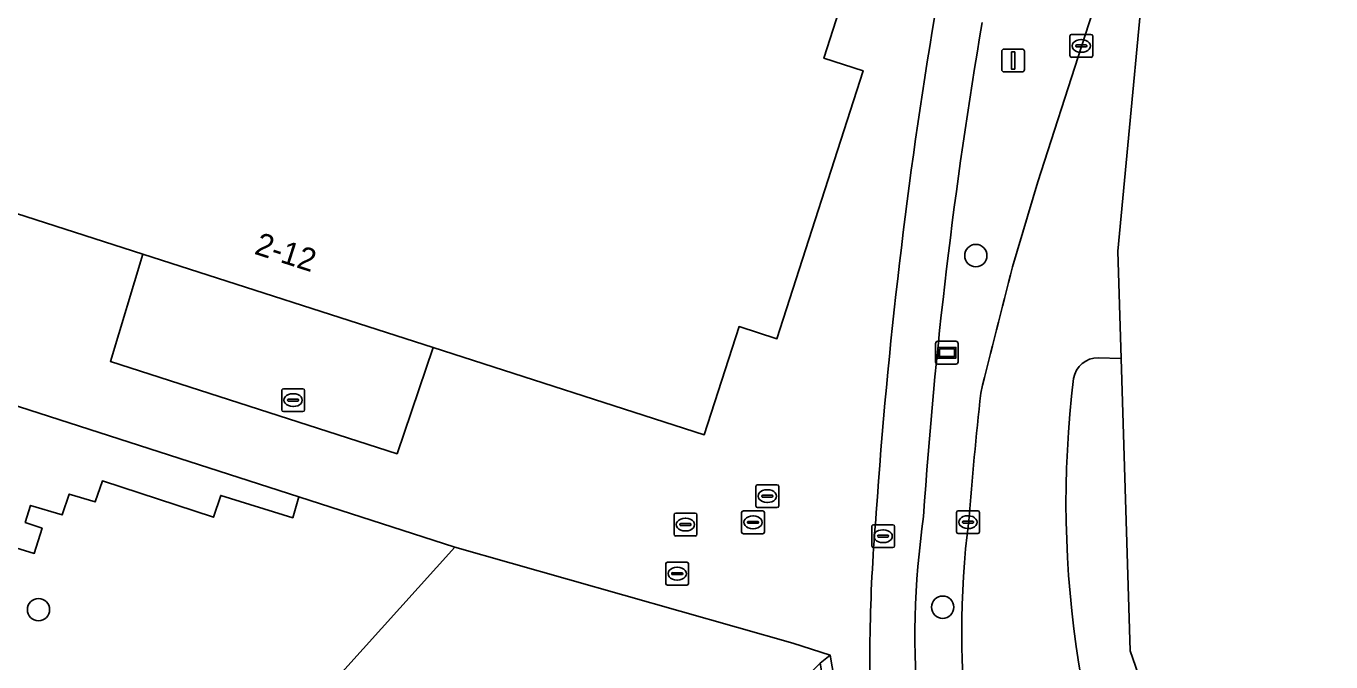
# Model space of a CAD drawing. Extents: x 160675 to 161153, y 383241 to 383714.
# Drawn here: x 161039 to 161096.1, y 383296.7 to 383324.6 of the extents above; entities that cross this region are included whole.
import ezdxf

# ---------------------------------------------------------------- set-up
doc = ezdxf.new("R2010")
doc.units = 0
for name, color, linetype in [('IMGEO_Berm_groen', 7, 'Continuous'), ('IMGEO_Boom', 7, 'Continuous'), ('IMGEO_Brandkraan', 7, 'Continuous'), ('IMGEO_Fietspad_gesloten', 7, 'Continuous'), ('IMGEO_Groenvoorziening', 7, 'Continuous'), ('IMGEO_Kolk', 7, 'Continuous'), ('IMGEO_Lichtmast', 7, 'Continuous'), ('IMGEO_Pand', 7, 'Continuous'), ('IMGEO_Pand_nummerreeks', 7, 'Continuous'), ('IMGEO_Reclamebord', 7, 'Continuous'), ('IMGEO_Rijbaan_lokaal_gesloten', 7, 'Continuous'), ('IMGEO_Rioolput', 7, 'Continuous'), ('IMGEO_Verkeerseiland_groen', 7, 'Continuous'), ('IMGEO_Voetpad_open', 7, 'Continuous')]:
    doc.layers.add(name, color=color, linetype=linetype)

msp = doc.modelspace()

# ---------------------------------------------------------------- linework, layer by layer
at = {"layer": 'IMGEO_Berm_groen'}
msp.add_lwpolyline([(161082.189, 383314.05), (161083.295, 383317.77), (161085.211, 383323.707), (161089.61, 383337.285), (161096.146, 383357.606)], dxfattribs=at)
for centre, radius, start, end in [((161292.407, 383288.685), 214.601, 170.32297, 176.14495), ((161519.479, 383201.174), 451.624, 165.52635, 166.25015), ((161266.822, 383288.222), 187.128, 173.77371, 175.49626), ((161115.333, 383297.8), 37.42, 171.8377, 198.7986), ((161117.973, 383298.123), 38.005, 172.7545, 202.1608)]:
    msp.add_arc(centre, radius, start, end, dxfattribs=at)
at = {"layer": 'IMGEO_Boom'}
for centre in [(161080.583, 383314.544), (161039.499, 383299.033), (161079.131, 383299.138)]:
    msp.add_circle(centre, 0.489, dxfattribs=at)
at = {"layer": 'IMGEO_Brandkraan'}
for p, q in [((161066.993, 383300.183), (161066.993, 383301.035)), ((161067.068, 383301.109), (161067.92, 383301.109)), ((161067.481, 383300.889), (161067.506, 383300.889)), ((161067.994, 383301.035), (161067.994, 383300.183)), ((161067.92, 383300.109), (161067.068, 383300.109)), ((161067.252, 383300.603), (161067.252, 383300.615)), ((161067.69, 383300.566), (161067.292, 383300.566)), ((161067.295, 383300.652), (161067.693, 383300.652)), ((161067.504, 383300.329), (161067.479, 383300.329)), ((161067.736, 383300.615), (161067.736, 383300.603))]:
    msp.add_line(p, q, dxfattribs=at)
for points in [[(161066.993, 383300.183), (161066.993, 383301.035)], [(161067.068, 383301.109), (161067.92, 383301.109)], [(161067.994, 383301.035), (161067.994, 383300.183)], [(161067.92, 383300.109), (161067.068, 383300.109)]]:
    msp.add_lwpolyline(points, dxfattribs=at)
for centre, radius, start, end in [((161067.07, 383301.033), 0.0765, 91.552, 178.448), ((161067.07, 383301.033), 0.0765, 91.552, 178.448), ((161067.918, 383301.033), 0.0765, 1.552, 88.448), ((161067.918, 383301.033), 0.0765, 1.552, 88.448), ((161067.07, 383300.185), 0.0765, 181.552, 268.448), ((161067.07, 383300.185), 0.0765, 181.552, 268.448), ((161067.292, 383300.612), 0.0403, 85.8775, 175.7526), ((161067.289, 383300.602), 0.0366, 178.938, 274.7102), ((161067.693, 383300.609), 0.043, 264.8664, 352.4533), ((161067.697, 383300.614), 0.0386, 1.7309, 96.639), ((161067.918, 383300.185), 0.0765, 271.552, 358.448), ((161067.918, 383300.185), 0.0765, 271.552, 358.448)]:
    msp.add_arc(centre, radius, start, end, dxfattribs=at)
for centre, major_axis, ratio, start_param, end_param in [((161067.48, 383300.609), (-0.387, 0.002), 0.722429, 4.712389, 7.853982), ((161067.505, 383300.609), (-0.39, 0.002), 0.717154, 1.570796, 4.712389)]:
    msp.add_ellipse(centre, major_axis=major_axis, ratio=ratio, start_param=start_param, end_param=end_param, dxfattribs=at)
at = {"layer": 'IMGEO_Fietspad_gesloten'}
for centre, radius, start, end in [((161299.542, 383288.005), 223.844, 170.47225, 176.08333), ((161292.407, 383288.685), 214.601, 170.32297, 176.14495), ((161155.631, 383296.511), 79.7, 175.11724, 182.3005), ((161115.333, 383297.8), 37.42, 171.8377, 198.7986)]:
    msp.add_arc(centre, radius, start, end, dxfattribs=at)
at = {"layer": 'IMGEO_Groenvoorziening'}
msp.add_lwpolyline([(161037.053, 383284.483), (161040.997, 383283.21), (161057.751, 383301.776), (161050.91, 383303.976), (161050.64, 383303.056), (161047.486, 383304.035), (161047.165, 383303.078), (161042.298, 383304.675), (161041.978, 383303.75), (161040.846, 383304.095), (161040.543, 383303.185), (161039.154, 383303.596), (161038.919, 383302.854), (161039.655, 383302.597), (161039.31, 383301.493), (161037.358, 383302.095)], dxfattribs=at)
at = {"layer": 'IMGEO_Kolk'}
for p, q in [((161084.703, 383323.305), (161084.703, 383324.157)), ((161084.778, 383324.231), (161085.63, 383324.231)), ((161085.704, 383324.157), (161085.704, 383323.305)), ((161084.962, 383323.725), (161084.962, 383323.737)), ((161085.4, 383323.688), (161085.002, 383323.688)), ((161085.005, 383323.774), (161085.403, 383323.774)), ((161085.191, 383324.011), (161085.216, 383324.011)), ((161085.446, 383323.737), (161085.446, 383323.725)), ((161085.63, 383323.231), (161084.778, 383323.231)), ((161085.214, 383323.451), (161085.189, 383323.451)), ((161050.233, 383308.712), (161051.085, 383308.712)), ((161050.158, 383307.786), (161050.158, 383308.638)), ((161050.417, 383308.206), (161050.417, 383308.218)), ((161050.855, 383308.169), (161050.457, 383308.169)), ((161050.46, 383308.255), (161050.858, 383308.255)), ((161050.646, 383308.492), (161050.671, 383308.492)), ((161050.901, 383308.218), (161050.901, 383308.206)), ((161051.159, 383308.638), (161051.159, 383307.786)), ((161051.085, 383307.712), (161050.233, 383307.712)), ((161050.669, 383307.932), (161050.644, 383307.932)), ((161067.355, 383302.333), (161067.355, 383303.185)), ((161067.43, 383303.259), (161068.282, 383303.259)), ((161067.843, 383303.039), (161067.868, 383303.039)), ((161068.356, 383303.185), (161068.356, 383302.333)), ((161079.737, 383302.439), (161079.737, 383303.291)), ((161079.812, 383303.365), (161080.664, 383303.365)), ((161080.225, 383303.145), (161080.25, 383303.145)), ((161080.738, 383303.291), (161080.738, 383302.439)), ((161067.614, 383302.753), (161067.614, 383302.765)), ((161068.052, 383302.716), (161067.654, 383302.716)), ((161067.657, 383302.802), (161068.055, 383302.802)), ((161067.866, 383302.479), (161067.841, 383302.479)), ((161068.098, 383302.765), (161068.098, 383302.753)), ((161079.996, 383302.859), (161079.996, 383302.871)), ((161080.434, 383302.822), (161080.036, 383302.822)), ((161080.039, 383302.908), (161080.437, 383302.908)), ((161080.248, 383302.585), (161080.223, 383302.585)), ((161080.48, 383302.871), (161080.48, 383302.859)), ((161068.282, 383302.259), (161067.43, 383302.259)), ((161080.664, 383302.365), (161079.812, 383302.365))]:
    msp.add_line(p, q, dxfattribs=at)
for points in [[(161084.703, 383323.305), (161084.703, 383324.157)], [(161084.778, 383324.231), (161085.63, 383324.231)], [(161085.704, 383324.157), (161085.704, 383323.305)], [(161085.63, 383323.231), (161084.778, 383323.231)], [(161050.233, 383308.712), (161051.085, 383308.712)], [(161050.158, 383307.786), (161050.158, 383308.638)], [(161051.159, 383308.638), (161051.159, 383307.786)], [(161051.085, 383307.712), (161050.233, 383307.712)], [(161067.355, 383302.333), (161067.355, 383303.185)], [(161067.43, 383303.259), (161068.282, 383303.259)], [(161068.356, 383303.185), (161068.356, 383302.333)], [(161079.737, 383302.439), (161079.737, 383303.291)], [(161079.812, 383303.365), (161080.664, 383303.365)], [(161080.738, 383303.291), (161080.738, 383302.439)], [(161068.282, 383302.259), (161067.43, 383302.259)], [(161080.664, 383302.365), (161079.812, 383302.365)]]:
    msp.add_lwpolyline(points, dxfattribs=at)
for centre, radius, start, end in [((161084.78, 383324.155), 0.0765, 91.552, 178.448), ((161084.78, 383324.155), 0.0765, 91.552, 178.448), ((161085.628, 383324.155), 0.0765, 1.552, 88.448), ((161085.628, 383324.155), 0.0765, 1.552, 88.448), ((161085.002, 383323.734), 0.0403, 85.8775, 175.7526), ((161084.999, 383323.724), 0.0366, 178.938, 274.7102), ((161085.403, 383323.731), 0.043, 264.8664, 352.4533), ((161085.407, 383323.736), 0.0386, 1.7309, 96.639), ((161084.78, 383323.307), 0.0765, 181.552, 268.448), ((161084.78, 383323.307), 0.0765, 181.552, 268.448), ((161085.628, 383323.307), 0.0765, 271.552, 358.448), ((161085.628, 383323.307), 0.0765, 271.552, 358.448), ((161050.235, 383308.636), 0.0765, 91.552, 178.448), ((161050.235, 383308.636), 0.0765, 91.552, 178.448), ((161051.083, 383308.636), 0.0765, 1.552, 88.448), ((161051.083, 383308.636), 0.0765, 1.552, 88.448), ((161050.457, 383308.215), 0.0403, 85.8775, 175.7526), ((161050.454, 383308.205), 0.0366, 178.938, 274.7102), ((161050.858, 383308.212), 0.043, 264.8664, 352.4533), ((161050.862, 383308.217), 0.0386, 1.7309, 96.639), ((161050.235, 383307.788), 0.0765, 181.552, 268.448), ((161050.235, 383307.788), 0.0765, 181.552, 268.448), ((161051.083, 383307.788), 0.0765, 271.552, 358.448), ((161051.083, 383307.788), 0.0765, 271.552, 358.448), ((161067.432, 383303.183), 0.0765, 91.552, 178.448), ((161067.432, 383303.183), 0.0765, 91.552, 178.448), ((161068.28, 383303.183), 0.0765, 1.552, 88.448), ((161068.28, 383303.183), 0.0765, 1.552, 88.448), ((161079.814, 383303.289), 0.0765, 91.552, 178.448), ((161079.814, 383303.289), 0.0765, 91.552, 178.448), ((161080.662, 383303.289), 0.0765, 1.552, 88.448), ((161080.662, 383303.289), 0.0765, 1.552, 88.448), ((161067.654, 383302.762), 0.0403, 85.8775, 175.7526), ((161067.651, 383302.752), 0.0366, 178.938, 274.7102), ((161068.055, 383302.759), 0.043, 264.8664, 352.4533), ((161068.059, 383302.764), 0.0386, 1.7309, 96.639), ((161079.814, 383302.441), 0.0765, 181.552, 268.448), ((161079.814, 383302.441), 0.0765, 181.552, 268.448), ((161080.036, 383302.868), 0.0403, 85.8775, 175.7526), ((161080.033, 383302.858), 0.0366, 178.938, 274.7102), ((161080.437, 383302.865), 0.043, 264.8664, 352.4533), ((161080.441, 383302.87), 0.0386, 1.7309, 96.639), ((161080.662, 383302.441), 0.0765, 271.552, 358.448), ((161080.662, 383302.441), 0.0765, 271.552, 358.448), ((161067.432, 383302.335), 0.0765, 181.552, 268.448), ((161067.432, 383302.335), 0.0765, 181.552, 268.448), ((161068.28, 383302.335), 0.0765, 271.552, 358.448), ((161068.28, 383302.335), 0.0765, 271.552, 358.448)]:
    msp.add_arc(centre, radius, start, end, dxfattribs=at)
for centre, major_axis, ratio, start_param, end_param in [((161085.19, 383323.731), (-0.387, 0.002), 0.722429, 4.712389, 7.853982), ((161085.215, 383323.731), (-0.39, 0.002), 0.717154, 1.570796, 4.712389), ((161050.645, 383308.212), (-0.387, 0.002), 0.722429, 4.712389, 7.853982), ((161050.67, 383308.212), (-0.39, 0.002), 0.717154, 1.570796, 4.712389), ((161067.842, 383302.759), (-0.387, 0.002), 0.722429, 4.712389, 7.853982), ((161067.867, 383302.759), (-0.39, 0.002), 0.717154, 1.570796, 4.712389), ((161080.224, 383302.865), (-0.387, 0.002), 0.722429, 4.712389, 7.853982), ((161080.249, 383302.865), (-0.39, 0.002), 0.717154, 1.570796, 4.712389)]:
    msp.add_ellipse(centre, major_axis=major_axis, ratio=ratio, start_param=start_param, end_param=end_param, dxfattribs=at)
at = {"layer": 'IMGEO_Lichtmast'}
for p, q in [((161081.82, 383323.594), (161082.61, 383323.594)), ((161082.61, 383323.594), (161081.82, 383323.594)), ((161081.72, 383322.694), (161081.72, 383323.494)), ((161081.72, 383323.494), (161081.72, 383322.694)), ((161082.71, 383323.494), (161082.71, 383322.694)), ((161082.71, 383322.694), (161082.71, 383323.494)), ((161082.61, 383322.594), (161081.82, 383322.594)), ((161081.82, 383322.594), (161082.61, 383322.594))]:
    msp.add_line(p, q, dxfattribs=at)
msp.add_lwpolyline([(161082.14, 383323.469), (161082.29, 383323.469), (161082.29, 383322.719), (161082.14, 383322.719), (161082.14, 383323.469)], dxfattribs=at)
for centre, start, end in [((161081.82, 383323.494), 90, 180), ((161081.82, 383323.494), 90, 180), ((161082.61, 383323.494), 0, 90), ((161082.61, 383323.494), 360, 90), ((161081.82, 383322.694), 180, 270), ((161081.82, 383322.694), 180, 270), ((161082.61, 383322.694), 270, 0), ((161082.61, 383322.694), 270, 0)]:
    msp.add_arc(centre, 0.1, start, end, dxfattribs=at)
at = {"layer": 'IMGEO_Pand'}
msp.add_lwpolyline([(160982.34, 383300.282), (160989.622, 383299.281), (160990.405, 383301.74), (160994.422, 383300.461), (161000, 383317.976), (161003.126, 383327.791), (161044.076, 383314.613), (161056.802, 383310.518), (161068.681, 383306.695), (161070.205, 383311.433), (161071.867, 383310.899), (161075.639, 383322.641), (161073.926, 383323.193), (161075.413, 383327.845)], dxfattribs=at)
at = {"layer": 'IMGEO_Reclamebord'}
for p, q in [((161078.819, 383309.889), (161078.819, 383310.689)), ((161078.819, 383310.689), (161078.819, 383309.889)), ((161078.919, 383310.789), (161079.709, 383310.789)), ((161079.709, 383310.789), (161078.919, 383310.789)), ((161079.809, 383310.689), (161079.809, 383309.889)), ((161079.809, 383309.889), (161079.809, 383310.689)), ((161079.709, 383309.789), (161078.919, 383309.789)), ((161078.919, 383309.789), (161079.709, 383309.789))]:
    msp.add_line(p, q, dxfattribs=at)
for points in [[(161078.92, 383310.521), (161079.708, 383310.521), (161079.708, 383310.057), (161078.92, 383310.057), (161078.92, 383310.521)], [(161078.985, 383310.456), (161078.985, 383310.122), (161079.643, 383310.122), (161079.643, 383310.456), (161078.985, 383310.456)]]:
    msp.add_lwpolyline(points, dxfattribs=at)
for centre, start, end in [((161078.919, 383310.689), 90, 180), ((161078.919, 383310.689), 90, 180), ((161079.709, 383310.689), 0, 90), ((161079.709, 383310.689), 360, 90), ((161078.919, 383309.889), 180, 270), ((161078.919, 383309.889), 180, 270), ((161079.709, 383309.889), 270, 0), ((161079.709, 383309.889), 270, 0)]:
    msp.add_arc(centre, 0.1, start, end, dxfattribs=at)
at = {"layer": 'IMGEO_Rijbaan_lokaal_gesloten'}
msp.add_lwpolyline([(161085.952, 383310.069), (161086.953, 383310.04), (161086.81, 383314.743), (161088.305, 383330.707), (161090.326, 383337.057), (161089.61, 383337.285), (161085.211, 383323.707), (161083.295, 383317.77), (161082.189, 383314.05)], dxfattribs=at)
for centre, radius, start, end in [((161519.479, 383201.174), 451.624, 165.52635, 166.25015), ((161085.949, 383308.967), 1.102, 89.8509, 169.7084), ((161129.557, 383303.726), 45.022, 173.0629, 205.0313), ((161266.822, 383288.222), 187.128, 173.77371, 175.49626), ((161117.973, 383298.123), 38.005, 172.7545, 202.1608)]:
    msp.add_arc(centre, radius, start, end, dxfattribs=at)
at = {"layer": 'IMGEO_Rioolput'}
for p, q in [((161070.941, 383303.58), (161070.941, 383304.432)), ((161071.016, 383304.506), (161071.868, 383304.506)), ((161071.429, 383304.286), (161071.454, 383304.286)), ((161071.942, 383304.432), (161071.942, 383303.58)), ((161071.2, 383304), (161071.2, 383304.012)), ((161071.638, 383303.963), (161071.24, 383303.963)), ((161071.243, 383304.049), (161071.641, 383304.049)), ((161071.452, 383303.726), (161071.427, 383303.726)), ((161071.684, 383304.012), (161071.684, 383304)), ((161070.318, 383302.431), (161070.318, 383303.283)), ((161070.393, 383303.357), (161071.245, 383303.357)), ((161070.806, 383303.137), (161070.831, 383303.137)), ((161071.868, 383303.506), (161071.016, 383303.506)), ((161071.319, 383303.283), (161071.319, 383302.431)), ((161070.577, 383302.851), (161070.577, 383302.863)), ((161071.015, 383302.814), (161070.617, 383302.814)), ((161070.62, 383302.9), (161071.018, 383302.9)), ((161070.829, 383302.577), (161070.804, 383302.577)), ((161071.061, 383302.863), (161071.061, 383302.851)), ((161076.02, 383301.824), (161076.02, 383302.676)), ((161076.095, 383302.75), (161076.947, 383302.75)), ((161076.508, 383302.53), (161076.533, 383302.53)), ((161077.021, 383302.676), (161077.021, 383301.824)), ((161071.245, 383302.357), (161070.393, 383302.357)), ((161076.279, 383302.244), (161076.279, 383302.256)), ((161076.717, 383302.207), (161076.319, 383302.207)), ((161076.322, 383302.293), (161076.72, 383302.293)), ((161076.531, 383301.97), (161076.506, 383301.97)), ((161076.763, 383302.256), (161076.763, 383302.244)), ((161076.947, 383301.75), (161076.095, 383301.75))]:
    msp.add_line(p, q, dxfattribs=at)
for points in [[(161070.941, 383303.58), (161070.941, 383304.432)], [(161071.016, 383304.506), (161071.868, 383304.506)], [(161071.942, 383304.432), (161071.942, 383303.58)], [(161070.318, 383302.431), (161070.318, 383303.283)], [(161070.393, 383303.357), (161071.245, 383303.357)], [(161071.868, 383303.506), (161071.016, 383303.506)], [(161071.319, 383303.283), (161071.319, 383302.431)], [(161076.02, 383301.824), (161076.02, 383302.676)], [(161076.095, 383302.75), (161076.947, 383302.75)], [(161077.021, 383302.676), (161077.021, 383301.824)], [(161071.245, 383302.357), (161070.393, 383302.357)], [(161076.947, 383301.75), (161076.095, 383301.75)]]:
    msp.add_lwpolyline(points, dxfattribs=at)
for centre, radius, start, end in [((161071.018, 383304.43), 0.0765, 91.552, 178.448), ((161071.018, 383304.43), 0.0765, 91.552, 178.448), ((161071.866, 383304.43), 0.0765, 1.552, 88.448), ((161071.866, 383304.43), 0.0765, 1.552, 88.448), ((161071.018, 383303.582), 0.0765, 181.552, 268.448), ((161071.018, 383303.582), 0.0765, 181.552, 268.448), ((161071.24, 383304.009), 0.0403, 85.8775, 175.7526), ((161071.237, 383303.999), 0.0366, 178.938, 274.7102), ((161071.641, 383304.006), 0.043, 264.8664, 352.4533), ((161071.645, 383304.011), 0.0386, 1.7309, 96.639), ((161071.866, 383303.582), 0.0765, 271.552, 358.448), ((161071.866, 383303.582), 0.0765, 271.552, 358.448), ((161070.395, 383303.281), 0.0765, 91.552, 178.448), ((161070.395, 383303.281), 0.0765, 91.552, 178.448), ((161071.243, 383303.281), 0.0765, 1.552, 88.448), ((161071.243, 383303.281), 0.0765, 1.552, 88.448), ((161070.395, 383302.433), 0.0765, 181.552, 268.448), ((161070.395, 383302.433), 0.0765, 181.552, 268.448), ((161070.617, 383302.86), 0.0403, 85.8775, 175.7526), ((161070.614, 383302.85), 0.0366, 178.938, 274.7102), ((161071.018, 383302.857), 0.043, 264.8664, 352.4533), ((161071.022, 383302.862), 0.0386, 1.7309, 96.639), ((161071.243, 383302.433), 0.0765, 271.552, 358.448), ((161071.243, 383302.433), 0.0765, 271.552, 358.448), ((161076.097, 383302.674), 0.0765, 91.552, 178.448), ((161076.097, 383302.674), 0.0765, 91.552, 178.448), ((161076.945, 383302.674), 0.0765, 1.552, 88.448), ((161076.945, 383302.674), 0.0765, 1.552, 88.448), ((161076.097, 383301.826), 0.0765, 181.552, 268.448), ((161076.097, 383301.826), 0.0765, 181.552, 268.448), ((161076.319, 383302.253), 0.0403, 85.8775, 175.7526), ((161076.316, 383302.243), 0.0366, 178.938, 274.7102), ((161076.72, 383302.25), 0.043, 264.8664, 352.4533), ((161076.724, 383302.255), 0.0386, 1.7309, 96.639), ((161076.945, 383301.826), 0.0765, 271.552, 358.448), ((161076.945, 383301.826), 0.0765, 271.552, 358.448)]:
    msp.add_arc(centre, radius, start, end, dxfattribs=at)
for centre, major_axis, ratio, start_param, end_param in [((161071.428, 383304.006), (-0.387, 0.002), 0.722429, 4.712389, 7.853982), ((161071.453, 383304.006), (-0.39, 0.002), 0.717154, 1.570796, 4.712389), ((161070.805, 383302.857), (-0.387, 0.002), 0.722429, 4.712389, 7.853982), ((161070.83, 383302.857), (-0.39, 0.002), 0.717154, 1.570796, 4.712389), ((161076.507, 383302.25), (-0.387, 0.002), 0.722429, 4.712389, 7.853982), ((161076.532, 383302.25), (-0.39, 0.002), 0.717154, 1.570796, 4.712389)]:
    msp.add_ellipse(centre, major_axis=major_axis, ratio=ratio, start_param=start_param, end_param=end_param, dxfattribs=at)
at = {"layer": 'IMGEO_Verkeerseiland_groen'}
msp.add_lwpolyline([(161092.359, 383282.818), (161087.341, 383297.234), (161086.953, 383310.04), (161085.952, 383310.069)], dxfattribs=at)
for centre, radius, start, end in [((161085.949, 383308.967), 1.102, 89.8509, 169.7084), ((161129.557, 383303.726), 45.022, 173.0629, 205.0313)]:
    msp.add_arc(centre, radius, start, end, dxfattribs=at)
at = {"layer": 'IMGEO_Voetpad_open'}
for points in [[(161075.413, 383327.845), (161073.926, 383323.193), (161075.639, 383322.641), (161071.867, 383310.899), (161070.205, 383311.433), (161068.681, 383306.695), (161056.802, 383310.518), (161055.215, 383305.86), (161042.651, 383309.908), (161044.076, 383314.613), (161003.126, 383327.791)], [(160988.155, 383261.661), (160988.114, 383261.392), (160988.425, 383261.349), (160990.337, 383261.053), (160991.153, 383263.864), (160998.889, 383288.05), (160999.79, 383290.864), (161008.359, 383317.657), (161020.455, 383313.768), (161029.994, 383310.701), (161033.388, 383309.609), (161050.91, 383303.976), (161057.751, 383301.776), (161072.558, 383297.57), (161074.2, 383297.033), (161075.504, 383289.465)], [(161037.358, 383302.095), (161039.31, 383301.493), (161039.655, 383302.597), (161038.919, 383302.854), (161039.154, 383303.596), (161040.543, 383303.185), (161040.846, 383304.095), (161041.978, 383303.75), (161042.298, 383304.675), (161047.165, 383303.078), (161047.486, 383304.035), (161050.64, 383303.056), (161050.91, 383303.976), (161033.388, 383309.609)], [(161074.037, 383289.174), (161072.883, 383295.884), (161073.332, 383296.264), (161073.766, 383296.688), (161074.2, 383297.033), (161072.558, 383297.57), (161057.751, 383301.776), (161040.997, 383283.21), (161038.901, 383280.887)], [(161075.504, 383289.465), (161074.2, 383297.033), (161073.766, 383296.688), (161075.006, 383289.36), (161077.165, 383279.743), (161082.212, 383261.104), (161082.664, 383261.245), (161077.716, 383279.668)]]:
    msp.add_lwpolyline(points, dxfattribs=at)
msp.add_lwpolyline([(161044.076, 383314.613), (161042.651, 383309.908), (161055.215, 383305.86), (161056.802, 383310.518)], close=True, dxfattribs=at)
for centre, radius, start, end in [((161299.542, 383288.005), 223.844, 170.47225, 176.08333), ((161155.631, 383296.511), 79.7, 175.11724, 182.3005)]:
    msp.add_arc(centre, radius, start, end, dxfattribs=at)

# ---------------------------------------------------------------- texts
at = {"layer": 'IMGEO_Pand_nummerreeks'}
msp.add_text('2-12', height=1, rotation=342.1638, dxfattribs=at).set_placement((161048.918, 383314.631))

doc.saveas('drawing.dxf')
